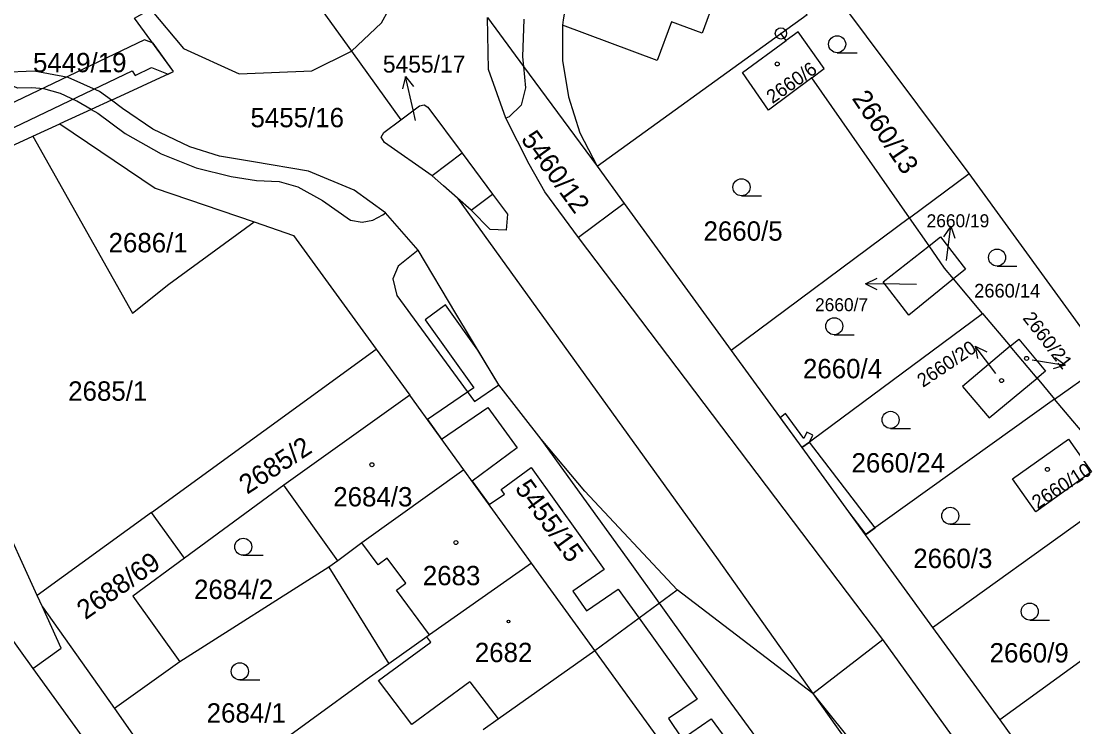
# Model space of a CAD drawing. Extents: x -821458 to -820266, y -1071458 to -1069826.
# Drawn here: x -820637.8 to -820545.4, y -1071392.4 to -1071330.5 of the extents above; entities that cross this region are included whole.
import ezdxf

# ---------------------------------------------------------------- set-up
doc = ezdxf.new("R2010")
doc.units = 0
for name, color, linetype in [('Vrstva 1', 7, 'Continuous'), ('Vrstva 13', 7, 'Continuous'), ('Vrstva 2', 7, 'Continuous'), ('Vrstva 3', 7, 'Continuous'), ('Vrstva 4', 7, 'Continuous'), ('Vrstva 5', 7, 'Continuous'), ('Vrstva 7', 7, 'Continuous'), ('Vrstva 8', 7, 'Continuous')]:
    doc.layers.add(name, color=color, linetype=linetype)

msp = doc.modelspace()

# ---------------------------------------------------------------- linework, layer by layer
at = {"layer": 'Vrstva 1'}
for p, q in [((-820587.2, -1071343.19), (-820571.04, -1071331.54)), ((-820570.59, -1071332.17), (-820571.04, -1071331.54)), ((-820559.74, -1071347.73), (-820568.32, -1071335.44)), ((-820636.76, -1071340.55), (-820634.4, -1071339.47)), ((-820651.69, -1071347.4), (-820636.76, -1071340.55)), ((-820587.2, -1071343.19), (-820584.82, -1071346.47)), ((-820559.74, -1071347.73), (-820554.5, -1071343.84)), ((-820542.47, -1071360.42), (-820554.5, -1071343.84)), ((-820584.82, -1071346.47), (-820588.84, -1071349.46)), ((-820584.82, -1071346.47), (-820575.42, -1071359.38)), ((-820636.39, -1071380.88), (-820651.69, -1071347.4)), ((-820559.74, -1071347.73), (-820575.42, -1071359.38)), ((-820558.02, -1071350.19), (-820559.74, -1071347.73)), ((-820562.09, -1071384.76), (-820588.84, -1071349.46)), ((-820553.32, -1071356.12), (-820555.87, -1071353.08)), ((-820569.2, -1071367.91), (-820553.32, -1071356.12)), ((-820553.32, -1071356.12), (-820550.89, -1071359.01)), ((-820548.54, -1071361.81), (-820550.89, -1071359.01)), ((-820626.34, -1071373.59), (-820606.6, -1071359.25)), ((-820606.6, -1071359.25), (-820603.66, -1071363.3)), ((-820575.42, -1071359.38), (-820569.2, -1071367.91)), ((-820546.99, -1071363.66), (-820542.47, -1071360.42)), ((-820548.54, -1071361.81), (-820546.99, -1071363.66)), ((-820603.66, -1071363.3), (-820614.72, -1071371.21)), ((-820598.9, -1071369.85), (-820603.66, -1071363.3)), ((-820546.99, -1071363.66), (-820563.63, -1071375.57)), ((-820540.54, -1071371.34), (-820546.99, -1071363.66)), ((-820569.2, -1071367.91), (-820563.63, -1071375.57)), ((-820592.96, -1071378.04), (-820598.9, -1071369.85)), ((-820614.72, -1071371.21), (-820623.44, -1071377.61)), ((-820609.98, -1071377.85), (-820614.72, -1071371.21)), ((-820557.71, -1071383.7), (-820540.54, -1071371.34)), ((-820626.34, -1071373.59), (-820636.39, -1071380.88)), ((-820623.44, -1071377.61), (-820626.34, -1071373.59)), ((-820563.63, -1071375.57), (-820557.71, -1071383.7)), ((-820610.76, -1071378.41), (-820623.85, -1071386.71)), ((-820609.98, -1071377.85), (-820610.76, -1071378.41)), ((-820610.76, -1071378.41), (-820605.49, -1071386.9)), ((-820587.38, -1071385.73), (-820592.96, -1071378.04)), ((-820534.12, -1071378.97), (-820551.8, -1071391.81)), ((-820635.93, -1071381.89), (-820636.39, -1071380.88)), ((-820587.38, -1071385.73), (-820580.16, -1071380.4)), ((-820568.23, -1071389.49), (-820580.16, -1071380.4)), ((-820635.93, -1071381.89), (-820629.59, -1071390.8)), ((-820557.71, -1071383.7), (-820551.8, -1071391.81)), ((-820568.23, -1071389.49), (-820562.09, -1071384.76)), ((-820578.44, -1071398.07), (-820587.38, -1071385.73)), ((-820623.85, -1071386.71), (-820629.59, -1071390.8)), ((-820629.59, -1071390.8), (-820623.29, -1071399.8)), ((-820551.8, -1071391.81), (-820541.996, -1071405.29))]:
    msp.add_line(p, q, dxfattribs=at)
for points in [[(-820579.87, -1071315.28), (-820582.56, -1071317.06), (-820584.9, -1071319.14), (-820586.78, -1071321.49), (-820588, -1071323.53), (-820589.23, -1071326.4), (-820589.84, -1071328.44), (-820590.16, -1071330.36), (-820590.22, -1071330.83), (-820590.24, -1071333.93), (-820589.7, -1071337.1), (-820588.71, -1071340.28), (-820587.2, -1071343.19)], [(-820554.5, -1071343.84), (-820570.3, -1071322.7), (-820574.1, -1071322.9)], [(-820571.04, -1071331.54), (-820568.75, -1071329.89), (-820574.1, -1071322.9)], [(-820627.84, -1071330.19), (-820626.42, -1071329.41), (-820615.71, -1071323.48), (-820608.76, -1071333.11), (-820604.43, -1071339.12)], [(-820629.87, -1071337.4), (-820624.4, -1071334.89), (-820627.84, -1071330.19)], [(-820596.83, -1071330.15), (-820593.66, -1071334.44), (-820587.2, -1071343.19)], [(-820588.84, -1071349.46), (-820591.79, -1071345.45), (-820593.17, -1071343.03), (-820595.21, -1071338.98), (-820596.72, -1071334.72), (-820596.83, -1071330.15)], [(-820568.32, -1071335.44), (-820572.14, -1071338.27), (-820574.43, -1071334.97), (-820570.59, -1071332.17)], [(-820568.32, -1071335.44), (-820567.24, -1071334.63), (-820569.54, -1071331.41), (-820570.59, -1071332.17)], [(-820629.87, -1071337.4), (-820630.92, -1071336.63), (-820633.66, -1071335.41), (-820636.65, -1071334.85), (-820639.5, -1071334.97), (-820642.22, -1071335.6), (-820646.76, -1071337.17), (-820651.91, -1071339.71), (-820660.24, -1071345.49), (-820688.88, -1071358.16), (-820705.99, -1071362.63), (-820707.35, -1071363.11), (-820711, -1071364.62), (-820713.77, -1071365.79), (-820719.56, -1071368.14), (-820729.538, -1071371.963)], [(-820629.87, -1071337.4), (-820631.64, -1071338.21), (-820634.4, -1071339.47)], [(-820580.16, -1071380.4), (-820588.28, -1071371.72), (-820592.11, -1071367.15), (-820595.84, -1071362.38), (-820599.6, -1071356.14), (-820602.9, -1071350.57), (-820605.79, -1071347.28), (-820608.53, -1071345.31), (-820612.56, -1071343.63), (-820617.37, -1071342.82), (-820620.38, -1071342.31), (-820622.97, -1071341.51), (-820626.24, -1071339.95), (-820628.88, -1071338.12), (-820629.87, -1071337.4)], [(-820604.43, -1071339.12), (-820602.8, -1071337.91), (-820602.4, -1071337.81), (-820602.07, -1071338.01), (-820599.05, -1071342.06), (-820596.39, -1071345.64), (-820595.07, -1071347.42), (-820595.19, -1071348.82), (-820596.59, -1071348.77), (-820598.27, -1071347.06), (-820599.46, -1071346.01)], [(-820634.4, -1071339.47), (-820626.02, -1071345.13), (-820617.33, -1071348.09)], [(-820599.46, -1071346.01), (-820600.69, -1071344.92), (-820601.69, -1071344.05), (-820605.88, -1071341.11), (-820606.16, -1071340.64), (-820605.94, -1071340.24), (-820604.43, -1071339.12)], [(-820636.76, -1071340.55), (-820628.02, -1071356.09), (-820624.83, -1071353.56), (-820617.33, -1071348.09)], [(-820599.46, -1071346.01), (-820576.56, -1071377.75), (-820568.23, -1071389.49)], [(-820617.33, -1071348.09), (-820613.86, -1071349.27), (-820606.6, -1071359.25)], [(-820558.02, -1071350.19), (-820557.03, -1071349.41), (-820554.83, -1071352.23), (-820555.87, -1071353.08)], [(-820555.87, -1071353.08), (-820559.79, -1071356.27), (-820562.06, -1071353.35), (-820558.02, -1071350.19)], [(-820555.87, -1071353.08), (-820556.66, -1071352.14), (-820558.02, -1071350.19)], [(-820550.89, -1071359.01), (-820555.08, -1071362.55), (-820552.75, -1071365.3), (-820548.54, -1071361.81)], [(-820550.89, -1071359.01), (-820550.13, -1071358.37), (-820547.79, -1071361.2), (-820548.54, -1071361.81)], [(-820545.77, -1071367.15), (-820543.74, -1071370.03), (-820548.64, -1071373.54), (-820550.69, -1071370.64), (-820545.77, -1071367.15)], [(-820598.9, -1071369.85), (-820607.86, -1071376.27), (-820609.98, -1071377.85)], [(-820623.44, -1071377.61), (-820627.99, -1071380.95), (-820623.85, -1071386.71)], [(-820592.96, -1071378.04), (-820601.91, -1071384.34), (-820602.15, -1071384.52), (-820605.49, -1071386.9)], [(-820636.76, -1071387.29), (-820634.27, -1071385.52), (-820635.93, -1071381.89)], [(-820653.43, -1071399.1), (-820656.81, -1071394.43), (-820640.28, -1071382.43), (-820636.76, -1071387.29)], [(-820545.726, -1071407.476), (-820562.09, -1071384.76)], [(-820597.2, -1071392.64), (-820595.89, -1071391.71), (-820587.38, -1071385.73)], [(-820636.76, -1071387.29), (-820609.95, -1071424.33), (-820631.03, -1071439.67), (-820644.44, -1071421.08), (-820639.9, -1071417.79), (-820653.43, -1071399.1)], [(-820605.49, -1071386.9), (-820607.39, -1071388.24), (-820617.53, -1071395.61), (-820623.29, -1071399.8)], [(-820568.23, -1071389.49), (-820555.51, -1071405.39), (-820551.51, -1071410.867)], [(-820568.23, -1071389.49), (-820552.602, -1071411.507)]]:
    msp.add_lwpolyline(points, dxfattribs=at)
at = {"layer": 'Vrstva 13'}
for points in [[(-820649.48, -1071345.07), (-820628.03, -1071334.83), (-820627.78, -1071335.23), (-820626.34, -1071334.52), (-820624.87, -1071335.11), (-820624.4, -1071334.89), (-820626.21, -1071332.41), (-820626.97, -1071332.11), (-820650.32, -1071343.25)], [(-820567.01, -1071401.8), (-820575.97, -1071389.59), (-820581.72, -1071381.55), (-820584.14, -1071378.18), (-820592.11, -1071367.15), (-820595.84, -1071362.38), (-820597.67, -1071359.34), (-820600.51, -1071355.38), (-820602.31, -1071356.68), (-820598.03, -1071362.65), (-820602.1, -1071365.45), (-820600.86, -1071367.16), (-820596.8, -1071364.37), (-820594.23, -1071367.92), (-820598.18, -1071370.84), (-820596.69, -1071372.9), (-820595.34, -1071372), (-820595.61, -1071371.57), (-820592.99, -1071369.64), (-820586.57, -1071378.6), (-820589.33, -1071380.51), (-820588.13, -1071382.25), (-820585.34, -1071380.32), (-820583.51, -1071382.87), (-820578.41, -1071390), (-820580.91, -1071391.7), (-820579.71, -1071393.46), (-820577.16, -1071391.72), (-820569.42, -1071402.27)]]:
    msp.add_lwpolyline(points, dxfattribs=at)
for points in [[(-820568.23, -1071366.82), (-820568.76, -1071366.55), (-820569.04, -1071367.11), (-820570.65, -1071364.9), (-820571.11, -1071365.29), (-820569.2, -1071367.91), (-820568.53, -1071367.42)], [(-820569.2, -1071367.91), (-820565.11, -1071373.54), (-820563.59, -1071375.54), (-820562.77, -1071374.96), (-820568.53, -1071367.42)]]:
    msp.add_lwpolyline(points, close=True, dxfattribs=at)
at = {"layer": 'Vrstva 3'}
for p, q in [((-820566.103, -1071333.24), (-820564.353, -1071333.24)), ((-820574.503, -1071345.8), (-820572.753, -1071345.8)), ((-820552.053, -1071351.97), (-820550.303, -1071351.97)), ((-820566.353, -1071358), (-820564.603, -1071358)), ((-820561.403, -1071366.22), (-820559.653, -1071366.22)), ((-820556.163, -1071374.64), (-820554.413, -1071374.64)), ((-820618.283, -1071377.36), (-820616.533, -1071377.36)), ((-820549.183, -1071383.05), (-820547.433, -1071383.05)), ((-820618.583, -1071388.3), (-820616.833, -1071388.3))]:
    msp.add_line(p, q, dxfattribs=at)
for centre in [(-820566.103, -1071332.49), (-820574.503, -1071345.05), (-820552.053, -1071351.22), (-820566.353, -1071357.25), (-820561.403, -1071365.47), (-820556.163, -1071373.89), (-820618.283, -1071376.61), (-820549.183, -1071382.3), (-820618.583, -1071387.55)]:
    msp.add_circle(centre, 0.75, dxfattribs=at)
at = {"layer": 'Vrstva 4'}
for p, q in [((-820574.86, -1071322.92), (-820577.97, -1071331.52)), ((-820606.13, -1071330.6), (-820604.21, -1071327.14)), ((-820626.42, -1071329.41), (-820623.54, -1071332.85)), ((-820593.63, -1071330.28), (-820593.74, -1071333.61)), ((-820608.76, -1071333.11), (-820606.13, -1071330.6)), ((-820581.92, -1071333.91), (-820590.22, -1071330.83)), ((-820580.66, -1071330.52), (-820581.92, -1071333.91)), ((-820577.97, -1071331.52), (-820580.66, -1071330.52)), ((-820623.54, -1071332.85), (-820618.63, -1071335.1)), ((-820612.26, -1071334.84), (-820608.76, -1071333.11)), ((-820593.74, -1071333.61), (-820593.66, -1071334.44)), ((-820618.63, -1071335.1), (-820612.26, -1071334.84)), ((-820593.66, -1071334.44), (-820593.48, -1071336.33)), ((-820593.48, -1071336.33), (-820593.86, -1071337.85)), ((-820631.64, -1071338.21), (-820631.06, -1071338.54)), ((-820631.06, -1071338.54), (-820628.65, -1071340.33)), ((-820593.86, -1071337.85), (-820594.93, -1071338.85)), ((-820594.93, -1071338.85), (-820595.21, -1071338.98)), ((-820628.65, -1071340.33), (-820625.48, -1071342.11)), ((-820625.48, -1071342.11), (-820622.41, -1071343.33)), ((-820599.05, -1071342.06), (-820601.69, -1071344.05)), ((-820622.41, -1071343.33), (-820619.34, -1071344.11)), ((-820619.34, -1071344.11), (-820617.12, -1071344.44)), ((-820617.12, -1071344.44), (-820615.14, -1071344.55)), ((-820615.14, -1071344.55), (-820613.48, -1071345)), ((-820613.48, -1071345), (-820611.32, -1071346.2)), ((-820598.27, -1071347.06), (-820596.39, -1071345.64)), ((-820611.32, -1071346.2), (-820608.87, -1071347.93)), ((-820608.87, -1071347.93), (-820607.83, -1071348.11)), ((-820607.83, -1071348.11), (-820606.89, -1071347.95)), ((-820606.89, -1071347.95), (-820606.02, -1071347.47)), ((-820606.02, -1071347.47), (-820605.79, -1071347.28)), ((-820602.9, -1071350.57), (-820604.68, -1071351.97)), ((-820604.68, -1071351.97), (-820605.15, -1071353.09)), ((-820605.15, -1071353.09), (-820604.8, -1071354.55)), ((-820604.8, -1071354.55), (-820597.95, -1071363.85)), ((-820597.95, -1071363.85), (-820595.84, -1071362.38)), ((-820606.44, -1071378.2), (-820607.86, -1071376.27)), ((-820605.63, -1071377.61), (-820606.44, -1071378.2)), ((-820604, -1071379.81), (-820605.63, -1071377.61)), ((-820604.81, -1071380.41), (-820604, -1071379.81)), ((-820601.91, -1071384.34), (-820604.81, -1071380.41)), ((-820598.37, -1071388.46), (-820595.89, -1071391.71))]:
    msp.add_line(p, q, dxfattribs=at)
for points in [[(-820631.64, -1071338.21), (-820632.91, -1071337.49), (-820634.33, -1071336.81), (-820635.8, -1071336.42), (-820636.85, -1071336.31), (-820638.12, -1071336.35), (-820639.03, -1071335.94), (-820639.5, -1071334.97)], [(-820606.39, -1071388.35), (-820601.81, -1071384.99), (-820602.15, -1071384.52)], [(-820598.37, -1071388.46), (-820603.48, -1071392.22), (-820606.39, -1071388.35)]]:
    msp.add_lwpolyline(points, dxfattribs=at)
at = {"layer": 'Vrstva 5'}
for centre, radius in [((-820571.367, -1071334.219), 0.175), ((-820549.457, -1071360.069), 0.175), ((-820551.657, -1071362.019), 0.175), ((-820606.977, -1071369.409), 0.175), ((-820547.627, -1071369.819), 0.175), ((-820599.597, -1071376.239), 0.175), ((-820594.985, -1071383.169), 0.117)]:
    msp.add_circle(centre, radius, dxfattribs=at)
at = {"layer": 'Vrstva 7'}
for p, q in [((-820604.035, -1071335.326), (-820604.298, -1071336.414)), ((-820603.36, -1071338.25), (-820604.035, -1071335.326)), ((-820604.035, -1071335.326), (-820603.322, -1071336.189)), ((-820603.14, -1071339.2), (-820603.36, -1071338.25)), ((-820556.124, -1071348.471), (-820556.743, -1071349.404)), ((-820556.49, -1071351.45), (-820556.124, -1071348.471)), ((-820556.124, -1071348.471), (-820555.749, -1071349.526)), ((-820556.5, -1071351.48), (-820556.49, -1071351.45)), ((-820563.611, -1071353.518), (-820562.6, -1071353.034)), ((-820560.61, -1071353.57), (-820563.611, -1071353.518)), ((-820563.611, -1071353.518), (-820562.618, -1071354.036)), ((-820559.12, -1071353.59), (-820560.61, -1071353.57)), ((-820552.16, -1071361.39), (-820553.966, -1071358.993)), ((-820553.966, -1071358.993), (-820552.963, -1071359.492)), ((-820553.966, -1071358.993), (-820553.763, -1071360.094)), ((-820548.97, -1071360.21), (-820546.065, -1071360.67)), ((-820546.065, -1071360.67), (-820547.111, -1071361.001)), ((-820546.065, -1071360.67), (-820546.958, -1071360.032))]:
    msp.add_line(p, q, dxfattribs=at)
at = {"layer": 'Vrstva 8'}
for radius in [0.5, 0.0303]:
    msp.add_circle((-820571.04, -1071331.54), radius, dxfattribs=at)

# ---------------------------------------------------------------- texts
at = {"layer": 'Vrstva 2'}
for s, height, p in [('5449/19', 1.7, (-820636.758, -1071334.95)), ('5455/17', 1.5, (-820606.016, -1071334.98)), ('5455/16', 1.7, (-820617.648, -1071339.779)), ('2660/5', 1.7, (-820577.845, -1071349.739)), ('2660/19', 1.139, (-820558.241, -1071348.559)), ('2686/1', 1.7, (-820630.115, -1071350.759)), ('2660/14', 1.2, (-820554.06, -1071354.729)), ('2660/7', 1.139, (-820568.044, -1071355.929)), ('2660/4', 1.7, (-820569.105, -1071361.82)), ('2685/1', 1.7, (-820633.665, -1071363.79)), ('2660/24', 1.7, (-820564.838, -1071370.09)), ('2684/3', 1.7, (-820610.375, -1071373.07)), ('2660/3', 1.7, (-820559.415, -1071378.479)), ('2683', 1.7, (-820602.507, -1071379.989)), ('2684/2', 1.7, (-820622.605, -1071381.2)), ('2682', 1.7, (-820597.937, -1071386.739)), ('2660/9', 1.7, (-820552.705, -1071386.769)), ('2684/1', 1.7, (-820621.495, -1071392.05))]:
    msp.add_text(s, height=height, dxfattribs=at).set_placement(p)
for s, height, rotation, p in [('2660/6', 1.2, 35, (-820571.785, -1071337.751)), ('2660/13', 1.7, 304, (-820564.85, -1071337.243)), ('5460/12', 1.7, 306, (-820593.943, -1071340.844)), ('2660/21', 1.2, 308, (-820549.852, -1071356.559)), ('2660/20', 1.2, 34, (-820558.564, -1071362.667)), ('2685/2', 1.7, 33, (-820617.939, -1071372.053)), ('2660/10', 1.2, 33, (-820548.493, -1071373.333)), ('5455/15', 1.7, 306, (-820594.473, -1071371.484)), ('2688/69', 1.7, 35, (-820632.146, -1071383.067))]:
    msp.add_text(s, height=height, rotation=rotation, dxfattribs=at).set_placement(p)

doc.saveas('drawing.dxf')
